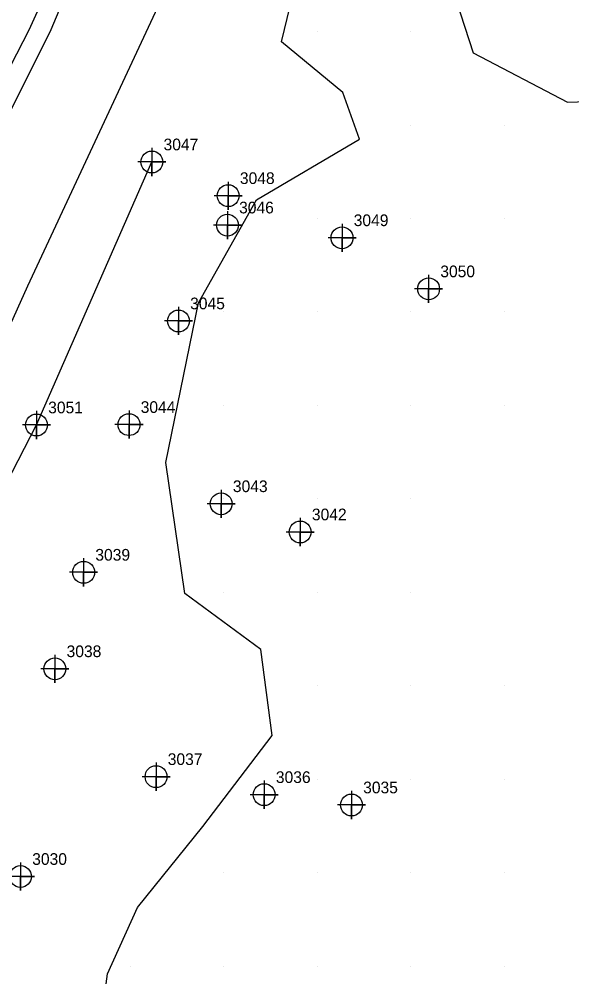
# Model space of a CAD drawing. Extents: x 2062781 to 2066835, y 358981 to 366501.
# Drawn here: x 2065273.3 to 2065391.6, y 363577.2 to 363782.2 of the extents above; entities that cross this region are included whole.
import ezdxf

# ---------------------------------------------------------------- set-up
doc = ezdxf.new("R2010")
doc.units = 0
for name, color, linetype in [('Exist DTM Breakline', 7, 'Continuous'), ('Exist DTM Breakline Cogo Number', 7, 'Continuous'), ('Exist DTM Breakline Cogo Point CELL', 7, 'Continuous'), ('Exist DTM Regular Point CELL', 7, 'Continuous'), ('Exist DTM Regular Point Cogo Number', 7, 'Continuous'), ('PH Exist DTM Breakline', 7, 'Continuous'), ('PH Exist DTM Point', 7, 'Continuous')]:
    doc.layers.add(name, color=color, linetype=linetype)

msp = doc.modelspace()

# ---------------------------------------------------------------- linework, layer by layer
at = {"layer": 'Exist DTM Breakline'}
for points in [[(2065277, 363695.34), (2065301.69, 363751.62)], [(2065004.64, 363156.66), (2065058.94, 363234.87), (2065104, 363334.19), (2065139.98, 363391.31), (2065168.9, 363454), (2065179.84, 363512.81), (2065195.44, 363548.73), (2065247.05, 363637.21), (2065277, 363695.34)]]:
    msp.add_lwpolyline(points, dxfattribs=at)
at = {"layer": 'Exist DTM Breakline Cogo Point CELL'}
for points in [[(2065301.69, 363754.62), (2065301.69, 363748.62), (2065301.69, 363751.62), (2065304.69, 363751.62), (2065298.69, 363751.62)], [(2065301.69, 363754.62), (2065301.69, 363748.62), (2065301.69, 363751.62), (2065304.69, 363751.62), (2065298.69, 363751.62)], [(2065301.69, 363754.62), (2065301.69, 363748.62), (2065301.69, 363751.62), (2065304.69, 363751.62), (2065298.69, 363751.62)], [(2065277, 363698.34), (2065277, 363692.34), (2065277, 363695.34), (2065280, 363695.34), (2065274, 363695.34)], [(2065277, 363698.34), (2065277, 363692.34), (2065277, 363695.34), (2065280, 363695.34), (2065274, 363695.34)], [(2065277, 363698.34), (2065277, 363692.34), (2065277, 363695.34), (2065280, 363695.34), (2065274, 363695.34)]]:
    msp.add_lwpolyline(points, dxfattribs=at)
for centre in [(2065301.69, 363751.62), (2065301.69, 363751.62), (2065301.69, 363751.62), (2065277, 363695.34), (2065277, 363695.34), (2065277, 363695.34)]:
    msp.add_circle(centre, 2.34, dxfattribs=at)
at = {"layer": 'Exist DTM Regular Point CELL'}
for points in [[(2065318.03, 363747.41), (2065318.03, 363741.41), (2065318.03, 363744.41), (2065321.03, 363744.41), (2065315.03, 363744.41)], [(2065317.86, 363741.12), (2065317.86, 363735.12), (2065317.86, 363738.12), (2065320.86, 363738.12), (2065314.86, 363738.12)], [(2065342.39, 363738.4), (2065342.39, 363732.4), (2065342.39, 363735.4), (2065345.39, 363735.4), (2065339.39, 363735.4)], [(2065360.92, 363727.46), (2065360.92, 363721.46), (2065360.92, 363724.46), (2065363.92, 363724.46), (2065357.92, 363724.46)], [(2065307.38, 363720.6), (2065307.38, 363714.6), (2065307.38, 363717.6), (2065310.38, 363717.6), (2065304.38, 363717.6)], [(2065296.8, 363698.42), (2065296.8, 363692.42), (2065296.8, 363695.42), (2065299.8, 363695.42), (2065293.8, 363695.42)], [(2065316.53, 363681.48), (2065316.53, 363675.48), (2065316.53, 363678.48), (2065319.53, 363678.48), (2065313.53, 363678.48)], [(2065333.44, 363675.44), (2065333.44, 363669.44), (2065333.44, 363672.44), (2065336.44, 363672.44), (2065330.44, 363672.44)], [(2065287.09, 363666.81), (2065287.09, 363660.81), (2065287.09, 363663.81), (2065290.09, 363663.81), (2065284.09, 363663.81)], [(2065280.94, 363646.16), (2065280.94, 363640.16), (2065280.94, 363643.16), (2065283.94, 363643.16), (2065277.94, 363643.16)], [(2065302.59, 363623.08), (2065302.59, 363617.08), (2065302.59, 363620.08), (2065305.59, 363620.08), (2065299.59, 363620.08)], [(2065325.73, 363619.23), (2065325.73, 363613.23), (2065325.73, 363616.23), (2065328.73, 363616.23), (2065322.73, 363616.23)], [(2065344.41, 363617.02), (2065344.41, 363611.02), (2065344.41, 363614.02), (2065347.41, 363614.02), (2065341.41, 363614.02)], [(2065273.58, 363601.71), (2065273.58, 363595.71), (2065273.58, 363598.71), (2065276.58, 363598.71), (2065270.58, 363598.71)]]:
    msp.add_lwpolyline(points, dxfattribs=at)
for centre in [(2065318.03, 363744.41), (2065317.86, 363738.12), (2065342.39, 363735.4), (2065360.92, 363724.46), (2065307.38, 363717.6), (2065296.8, 363695.42), (2065316.53, 363678.48), (2065333.44, 363672.44), (2065287.09, 363663.81), (2065280.94, 363643.16), (2065302.59, 363620.08), (2065325.73, 363616.23), (2065344.41, 363614.02), (2065273.58, 363598.71)]:
    msp.add_circle(centre, 2.34, dxfattribs=at)
at = {"layer": 'PH Exist DTM Breakline'}
for points in [[(2065018.95, 363181.82), (2065022.1, 363187.82), (2065046.03, 363241.26), (2065089.78, 363328.41), (2065120.97, 363386.96), (2065150.31, 363442.38), (2065162.49, 363482.96), (2065192.28, 363545.18), (2065222.26, 363610.9), (2065245.42, 363659.04), (2065275.12, 363725.13), (2065314.36, 363809.32), (2065348.05, 363874.1), (2065368.99, 363916.64)], [(2065322.9, 363875.89), (2065319.89, 363870.1), (2065314.87, 363858.37), (2065309.91, 363848.99), (2065302.92, 363834.99), (2065297.06, 363823.8), (2065291.87, 363812.53), (2065287.33, 363803.98), (2065283.36, 363797), (2065278.93, 363787.75), (2065275.34, 363779.86), (2065271.45, 363772.2), (2065267.71, 363765.62), (2065262.27, 363755.38), (2065258.31, 363747.5), (2065255.51, 363741.53), (2065254.67, 363739.82)], [(2065288.83, 363552.56), (2065292.22, 363577.86), (2065298.65, 363592.07), (2065312.6, 363609.4), (2065327.42, 363628.86), (2065325.02, 363647.29), (2065308.77, 363659.27), (2065304.69, 363687.28), (2065311.66, 363721.5), (2065324.07, 363743.51), (2065346.16, 363756.5), (2065342.56, 363766.47), (2065329.47, 363777.34), (2065336.84, 363807.9), (2065355.91, 363830.29), (2065363.07, 363821.41), (2065364.96, 363791.94), (2065370.42, 363774.96), (2065390.62, 363764.4), (2065425.12, 363765.57)], [(2065268.6, 363756.9), (2065280.11, 363779.98), (2065283.54, 363788.19)]]:
    msp.add_lwpolyline(points, dxfattribs=at)
at = {"layer": 'PH Exist DTM Point'}
for p, q in [((2065337.11, 363779.52), (2065337.11, 363779.52)), ((2065357.11, 363779.52), (2065357.11, 363779.52)), ((2065357.11, 363759.52), (2065357.11, 363759.52)), ((2065377.11, 363759.52), (2065377.11, 363759.52)), ((2065337.11, 363739.52), (2065337.11, 363739.52)), ((2065357.11, 363739.52), (2065357.11, 363739.52)), ((2065377.11, 363739.52), (2065377.11, 363739.52)), ((2065316.97, 363719.54), (2065316.97, 363719.54)), ((2065337.11, 363719.52), (2065337.11, 363719.52)), ((2065357.11, 363719.52), (2065357.11, 363719.52)), ((2065377.11, 363719.52), (2065377.11, 363719.52)), ((2065317.11, 363699.52), (2065317.11, 363699.52)), ((2065337.11, 363699.52), (2065337.11, 363699.52)), ((2065357.11, 363699.52), (2065357.11, 363699.52)), ((2065377.11, 363699.52), (2065377.11, 363699.52)), ((2065317.11, 363679.52), (2065317.11, 363679.52)), ((2065337.11, 363679.52), (2065337.11, 363679.52)), ((2065357.11, 363679.52), (2065357.11, 363679.52)), ((2065317.11, 363659.52), (2065317.11, 363659.52)), ((2065337.11, 363659.52), (2065337.11, 363659.52)), ((2065357.11, 363659.52), (2065357.11, 363659.52)), ((2065337.11, 363639.52), (2065337.11, 363639.52)), ((2065357.11, 363639.52), (2065357.11, 363639.52)), ((2065377.11, 363639.52), (2065377.11, 363639.52)), ((2065337.11, 363619.52), (2065337.11, 363619.52)), ((2065357.11, 363619.52), (2065357.11, 363619.52)), ((2065377.11, 363619.52), (2065377.11, 363619.52)), ((2065317.11, 363599.52), (2065317.11, 363599.52)), ((2065337.11, 363599.52), (2065337.11, 363599.52)), ((2065357.11, 363599.52), (2065357.11, 363599.52)), ((2065377.11, 363599.52), (2065377.11, 363599.52)), ((2065297.11, 363579.52), (2065297.11, 363579.52)), ((2065317.11, 363579.52), (2065317.11, 363579.52)), ((2065337.11, 363579.52), (2065337.11, 363579.52)), ((2065357.11, 363579.52), (2065357.11, 363579.52)), ((2065377.11, 363579.52), (2065377.11, 363579.52))]:
    msp.add_line(p, q, dxfattribs=at)

# ---------------------------------------------------------------- texts
at = {"layer": 'Exist DTM Breakline Cogo Number'}
for s, p in [('3047', (2065304.19, 363754.12)), ('3047', (2065304.19, 363754.12)), ('3047', (2065304.19, 363754.12)), ('3051', (2065279.5, 363697.84)), ('3051', (2065279.5, 363697.84)), ('3051', (2065279.5, 363697.84))]:
    msp.add_text(s, height=2.5, dxfattribs=at).set_placement(p)
at = {"layer": 'Exist DTM Regular Point Cogo Number'}
for s, p in [('3048', (2065320.53, 363746.91)), ('3048', (2065320.53, 363746.91)), ('3048', (2065320.53, 363746.91)), ('3046', (2065320.36, 363740.62)), ('3046', (2065320.36, 363740.62)), ('3046', (2065320.36, 363740.62)), ('3049', (2065344.89, 363737.9)), ('3049', (2065344.89, 363737.9)), ('3049', (2065344.89, 363737.9)), ('3050', (2065363.42, 363726.96)), ('3050', (2065363.42, 363726.96)), ('3050', (2065363.42, 363726.96)), ('3045', (2065309.88, 363720.1)), ('3045', (2065309.88, 363720.1)), ('3045', (2065309.88, 363720.1)), ('3044', (2065299.3, 363697.92)), ('3044', (2065299.3, 363697.92)), ('3044', (2065299.3, 363697.92)), ('3043', (2065319.03, 363680.98)), ('3043', (2065319.03, 363680.98)), ('3043', (2065319.03, 363680.98)), ('3042', (2065335.94, 363674.94)), ('3042', (2065335.94, 363674.94)), ('3042', (2065335.94, 363674.94)), ('3039', (2065289.59, 363666.31)), ('3039', (2065289.59, 363666.31)), ('3039', (2065289.59, 363666.31)), ('3038', (2065283.44, 363645.66)), ('3038', (2065283.44, 363645.66)), ('3038', (2065283.44, 363645.66)), ('3037', (2065305.09, 363622.58)), ('3037', (2065305.09, 363622.58)), ('3037', (2065305.09, 363622.58)), ('3036', (2065328.23, 363618.73)), ('3036', (2065328.23, 363618.73)), ('3036', (2065328.23, 363618.73)), ('3035', (2065346.91, 363616.52)), ('3035', (2065346.91, 363616.52)), ('3035', (2065346.91, 363616.52)), ('3030', (2065276.08, 363601.21)), ('3030', (2065276.08, 363601.21)), ('3030', (2065276.08, 363601.21))]:
    msp.add_text(s, height=2.5, dxfattribs=at).set_placement(p)

doc.saveas('drawing.dxf')
